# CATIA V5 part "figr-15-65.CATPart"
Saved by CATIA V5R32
Part number: Part1
Bounding box of the stored display mesh (mm): x -92.936 to 49.742, y -31.904 to 31.904, z 0 to 63.808
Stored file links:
  D:\PROJECTS\Project 2022\CATIA V5 6R 2022\Resources\Part Files\c15_catia_v5_6r2022_prt\figr-15-65.CATPart
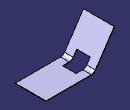
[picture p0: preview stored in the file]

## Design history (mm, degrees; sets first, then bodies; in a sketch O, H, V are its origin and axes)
SheetMetalParameters1: Thickness 1, BendRadius 10, KFactor 0.5 {= log(min(100,max(20*SheetMetalParameters1.BendRadius,SheetMetalParameters1.Thickness)/SheetMetalParameters1.Thickness))/log(100)/2}, ReliefRadialLength 1, ReliefAxialLength 2, MinimumBendRadius 0
Body1 (main body)
  Sketch1 on xy-plane, origin (0, 0, 0), H (1, 0, 0), V (0, 1, 0)
    line L1 (49.7419, 31.9042) -> (49.7419, -31.9042)
    line L2 (49.7419, -31.9042) -> (-49.7419, -31.9042)
    line L3 (-49.7419, -31.9042) -> (-49.7419, 31.9042)
    line L4 (-49.7419, 31.9042) -> (49.7419, 31.9042)
    vertical: L1 V, L3 V
    horizontal: L2 H, L4 H
    equidistance: L1 L3 O, L2 L4 O
  Wall1: Thickness 1, Profile Sketch1
  d_NewWallOnEdge1: NewWallOnEdge_Edge edge [face of Wall1 | face of Wall1], NewWallOnEdge_Length 63.8083, NewWallOnEdge_HeightLimitOffset 0, NewWallOnEdge_WidthOffset1 0, NewWallOnEdge_WidthOffset2 0, NewWallOnEdge_Angle 124, NewWallOnEdge_BendRadiusValue 10 {= SheetMetalParameters1.BendRadius}, NewWallOnEdge_BendTable SheetMetalParameters1, KFacteur 0.5 {= log(min(100,max(20*d_NewWallOnEdge1.Radius,SheetMetalParameters1.Thickness)/SheetMetalParameters1.Thickness))/log(100)/2}
  Sketch2 on face of d_NewWallOnEdge1, origin (0, 0, 1), H (1, 0, 0), V (0, 1, 0)
    point P1 (-49.1841, 0)
    line L1 (-30.5497, 14.1437) -> (-30.5497, -14.1437)
    line L2 (-30.5497, -14.1437) -> (-67.8185, -14.1437)
    line L3 (-67.8185, -14.1437) -> (-67.8185, 14.1437)
    line L4 (-67.8185, 14.1437) -> (-30.5497, 14.1437)
    coincidence: P1 H
    vertical: L1 V, L3 V
    horizontal: L2 H, L4 H
    equidistance: L1 L3 P1, L2 L4 P1
  CutOut1: Direction Sketch2, EndLimit through (limit type 2), Orientation true, Profile Sketch2, StartLimit through (limit type 2)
